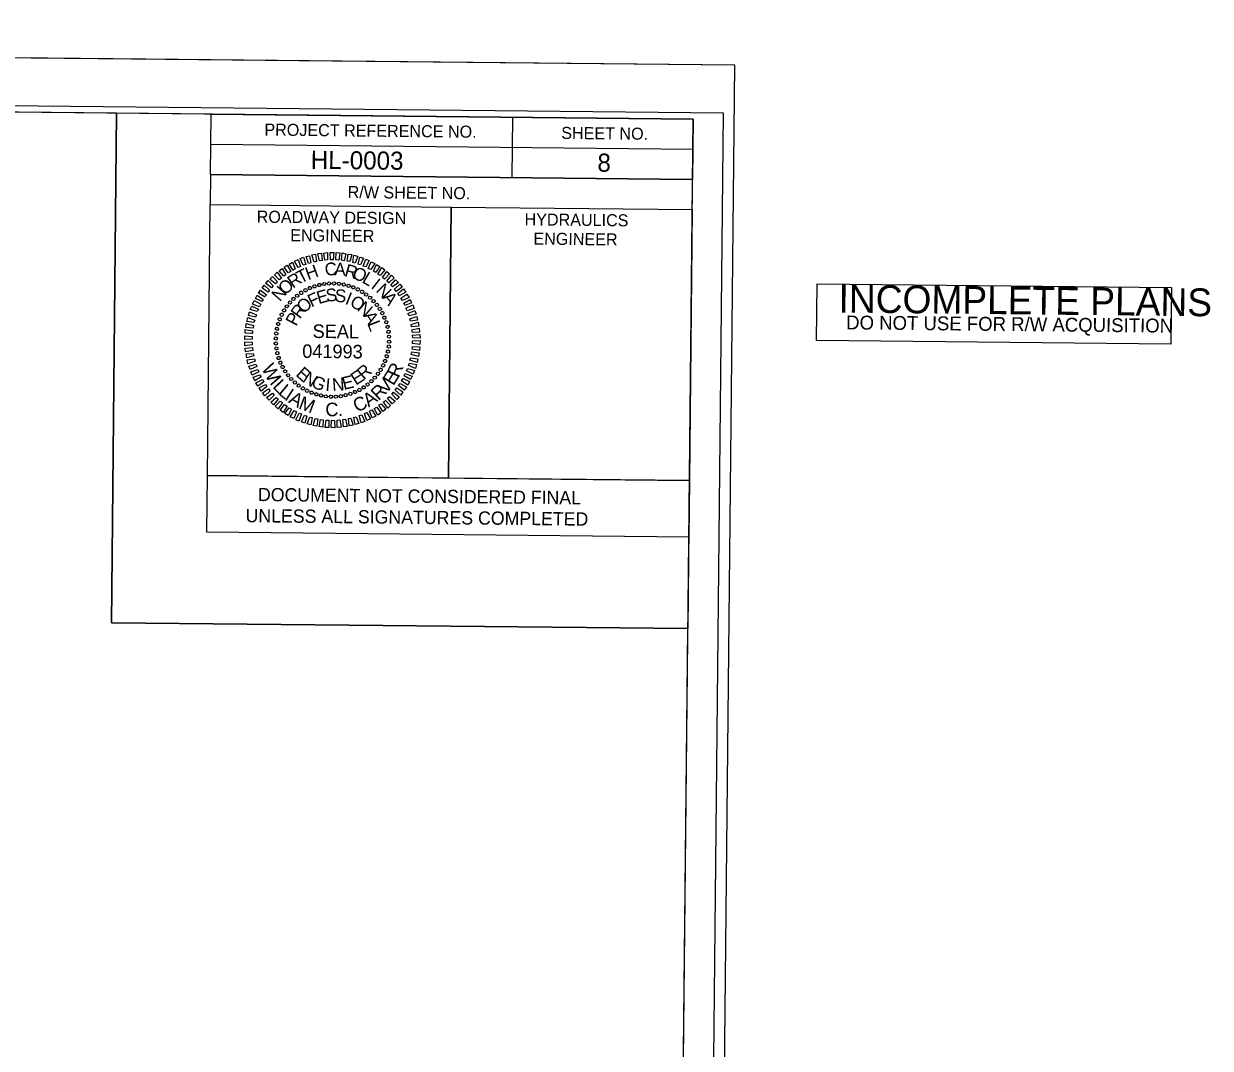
# Model space of a CAD drawing. Extents: x 928111 to 937215, y 684176 to 686530.
# Drawn here: x 934364.7 to 934857, y 684862.8 to 685288 of the extents above; entities that cross this region are included whole.
import ezdxf

# ---------------------------------------------------------------- set-up
doc = ezdxf.new("R2010")
doc.units = 0
for name, color, linetype in [('Default', 7, 'Continuous'), ('Sheet Cutting Line CELL', 7, 'Continuous'), ('Sheet Data Field CELL', 7, 'Continuous'), ('Sheet Plan CELL', 7, 'Continuous'), ('Sheet Plan Layout CELL', 7, 'Continuous'), ('Sheet Plot Border Inside CELL', 7, 'Continuous'), ('Sheet Plot Border Outside CELL', 7, 'Continuous')]:
    doc.layers.add(name, color=color, linetype=linetype)

msp = doc.modelspace()

# ---------------------------------------------------------------- linework, layer by layer
at = {"layer": 'Default'}
for p, q in [((934489.37, 685179.94), (934489.37, 685179.94)), ((934491.39, 685180.2), (934491.39, 685180.2)), ((934493.45, 685180.23), (934493.45, 685180.23)), ((934495.51, 685180.06), (934495.51, 685180.06)), ((934478.17, 685175.18), (934478.17, 685175.18)), ((934479.82, 685176.33), (934479.82, 685176.33)), ((934481.61, 685177.39), (934481.61, 685177.39)), ((934483.45, 685178.31), (934483.45, 685178.31)), ((934485.33, 685179.04), (934485.33, 685179.04)), ((934487.31, 685179.59), (934487.31, 685179.59)), ((934497.53, 685179.72), (934497.53, 685179.72)), ((934499.49, 685179.27), (934499.49, 685179.27)), ((934501.45, 685178.6), (934501.45, 685178.6)), ((934503.32, 685177.73), (934503.32, 685177.73)), ((934505.14, 685176.78), (934505.14, 685176.78)), ((934506.81, 685175.59), (934506.81, 685175.59)), ((934473.9, 685170.72), (934473.9, 685170.72)), ((934475.18, 685172.35), (934475.18, 685172.35)), ((934476.61, 685173.79), (934476.61, 685173.79)), ((934508.44, 685174.31), (934508.44, 685174.31)), ((934509.88, 685172.89), (934509.88, 685172.89)), ((934511.27, 685171.32), (934511.27, 685171.32)), ((934470.89, 685165.36), (934470.89, 685165.36)), ((934471.76, 685167.23), (934471.76, 685167.23)), ((934472.71, 685169.05), (934472.71, 685169.05)), ((934512.42, 685169.67), (934512.42, 685169.67)), ((934513.48, 685167.88), (934513.48, 685167.88)), ((934514.4, 685166.04), (934514.4, 685166.04)), ((934469.78, 685161.44), (934469.78, 685161.44)), ((934470.22, 685163.4), (934470.22, 685163.4)), ((934515.13, 685164.16), (934515.13, 685164.16)), ((934515.68, 685162.18), (934515.68, 685162.18)), ((934469.27, 685157.36), (934469.27, 685157.36)), ((934469.29, 685155.3), (934469.29, 685155.3)), ((934469.43, 685159.42), (934469.43, 685159.42)), ((934492.79, 685156.7), (934492.79, 685156.7)), ((934516.03, 685160.12), (934516.03, 685160.12)), ((934516.29, 685158.1), (934516.29, 685158.1)), ((934516.32, 685156.04), (934516.32, 685156.04)), ((934469.55, 685153.28), (934469.55, 685153.28)), ((934469.91, 685151.21), (934469.91, 685151.21)), ((934515.81, 685151.96), (934515.81, 685151.96)), ((934516.16, 685153.98), (934516.16, 685153.98)), ((934470.45, 685149.24), (934470.45, 685149.24)), ((934471.18, 685147.36), (934471.18, 685147.36)), ((934472.1, 685145.52), (934472.1, 685145.52)), ((934513.83, 685146.17), (934513.83, 685146.17)), ((934514.69, 685148.04), (934514.69, 685148.04)), ((934515.36, 685150), (934515.36, 685150)), ((934473.16, 685143.73), (934473.16, 685143.73)), ((934474.31, 685142.08), (934474.31, 685142.08)), ((934475.7, 685140.51), (934475.7, 685140.51)), ((934510.4, 685141.05), (934510.4, 685141.05)), ((934511.68, 685142.68), (934511.68, 685142.68)), ((934512.87, 685144.35), (934512.87, 685144.35)), ((934477.14, 685139.09), (934477.14, 685139.09)), ((934478.77, 685137.81), (934478.77, 685137.81)), ((934480.44, 685136.62), (934480.44, 685136.62)), ((934482.26, 685135.67), (934482.26, 685135.67)), ((934503.97, 685136.01), (934503.97, 685136.01)), ((934505.76, 685137.07), (934505.76, 685137.07)), ((934507.42, 685138.22), (934507.42, 685138.22)), ((934508.98, 685139.61), (934508.98, 685139.61)), ((934484.13, 685134.8), (934484.13, 685134.8)), ((934486.09, 685134.13), (934486.09, 685134.13)), ((934488.06, 685133.68), (934488.06, 685133.68)), ((934490.07, 685133.34), (934490.07, 685133.34)), ((934492.13, 685133.17), (934492.13, 685133.17)), ((934494.19, 685133.2), (934494.19, 685133.2)), ((934496.21, 685133.46), (934496.21, 685133.46)), ((934498.28, 685133.81), (934498.28, 685133.81)), ((934500.25, 685134.36), (934500.25, 685134.36)), ((934502.13, 685135.09), (934502.13, 685135.09))]:
    msp.add_line(p, q, dxfattribs=at)
for points in [[(934478.52, 685186.8), (934477.05, 685189.44), (934478.51, 685190.08), (934479.56, 685187.21)], [(934480.59, 685187.76), (934479.4, 685190.49), (934480.81, 685191.04), (934481.77, 685188.03)], [(934482.9, 685188.49), (934481.85, 685191.31), (934483.3, 685191.72), (934483.88, 685188.81)], [(934485.15, 685189.08), (934484.2, 685192.04), (934485.8, 685192.35), (934486.14, 685189.3)], [(934487.41, 685189.57), (934486.69, 685192.58), (934488.24, 685192.7), (934488.53, 685189.7)], [(934489.66, 685189.83), (934489.18, 685192.83), (934490.77, 685193), (934490.79, 685189.96)], [(934492.01, 685190.04), (934491.8, 685193.09), (934493.35, 685193.02), (934493.13, 685189.98)], [(934494.26, 685189.97), (934494.29, 685193.01), (934495.83, 685192.95), (934495.38, 685189.91)], [(934496.6, 685189.8), (934496.82, 685192.85), (934498.36, 685192.55), (934497.72, 685189.6)], [(934498.84, 685189.41), (934499.3, 685192.4), (934500.84, 685192.15), (934499.97, 685189.25)], [(934501.23, 685188.87), (934501.73, 685191.91), (934503.32, 685191.52), (934502.21, 685188.62)], [(934503.47, 685188.23), (934504.21, 685191.13), (934505.65, 685190.65), (934504.45, 685187.89)], [(934505.57, 685187.37), (934506.68, 685190.31), (934507.99, 685189.73), (934506.65, 685187.03)], [(934470.73, 685181.72), (934468.69, 685183.81), (934469.83, 685184.92), (934471.63, 685182.37)], [(934472.62, 685183.16), (934470.63, 685185.43), (934471.91, 685186.4), (934473.52, 685183.76)], [(934474.42, 685184.55), (934472.71, 685186.95), (934473.94, 685187.83), (934475.46, 685185.1)], [(934476.49, 685185.7), (934474.78, 685188.24), (934476.25, 685188.98), (934477.39, 685186.25)], [(934507.67, 685186.46), (934508.87, 685189.21), (934510.32, 685188.54), (934508.7, 685185.93)], [(934509.82, 685185.36), (934511.11, 685188.01), (934512.51, 685187.2), (934510.7, 685184.78)], [(934511.63, 685184.07), (934513.3, 685186.77), (934514.51, 685185.78), (934512.66, 685183.5)], [(934513.54, 685182.65), (934515.3, 685185.21), (934516.51, 685184.16), (934514.43, 685181.98)], [(934467.51, 685178.33), (934465.09, 685180.19), (934466.14, 685181.4), (934468.18, 685179.17)], [(934469.17, 685180.1), (934466.8, 685182.04), (934467.98, 685183.11), (934469.93, 685180.84)], [(934515.31, 685181.17), (934517.25, 685183.59), (934518.37, 685182.46), (934516.19, 685180.46)], [(934516.98, 685179.52), (934519.02, 685181.7), (934520.13, 685180.56), (934517.67, 685178.76)], [(934518.6, 685177.81), (934520.78, 685179.9), (934521.75, 685178.62), (934519.25, 685176.87)], [(934463.52, 685172.7), (934460.86, 685173.9), (934461.57, 685175.35), (934464.09, 685173.59)], [(934464.66, 685174.71), (934462.05, 685176.14), (934463, 685177.44), (934465.42, 685175.54)], [(934466.09, 685176.57), (934463.57, 685178.19), (934464.48, 685179.54), (934466.71, 685177.45)], [(934519.99, 685175.97), (934522.31, 685177.91), (934523.18, 685176.55), (934520.54, 685175.07)], [(934521.19, 685174.04), (934523.69, 685175.79), (934524.57, 685174.38), (934521.84, 685173.09)], [(934461.6, 685168.5), (934458.7, 685169.38), (934459.32, 685170.82), (934462.12, 685169.48)], [(934462.56, 685170.56), (934459.66, 685171.66), (934460.38, 685173.11), (934463.04, 685171.58)], [(934522.39, 685171.96), (934525.03, 685173.57), (934525.62, 685172.11), (934522.94, 685171.06)], [(934523.3, 685169.94), (934526.08, 685171.31), (934526.68, 685169.81), (934523.76, 685168.9)], [(934460.24, 685164.02), (934457.34, 685164.42), (934457.68, 685166.01), (934460.62, 685165)], [(934460.87, 685166.26), (934457.97, 685166.9), (934458.32, 685168.44), (934461.26, 685167.24)], [(934524.12, 685167.72), (934527, 685168.91), (934527.5, 685167.45), (934524.58, 685166.73)], [(934524.85, 685165.47), (934527.86, 685166.51), (934528.13, 685164.96), (934525.17, 685164.48)], [(934459.58, 685159.38), (934456.54, 685159.51), (934456.65, 685161.05), (934459.69, 685160.51)], [(934459.84, 685161.63), (934456.84, 685161.94), (934457.05, 685163.53), (934460.09, 685162.75)], [(934525.39, 685163.21), (934528.35, 685164.07), (934528.62, 685162.47), (934525.66, 685162.22)], [(934525.79, 685160.96), (934528.84, 685161.58), (934528.97, 685159.99), (934525.97, 685159.83)], [(934459.53, 685154.7), (934456.48, 685154.35), (934456.41, 685155.95), (934459.45, 685155.82)], [(934459.51, 685157.04), (934456.46, 685156.93), (934456.48, 685158.52), (934459.52, 685158.16)], [(934526.05, 685158.7), (934529.1, 685159.05), (934529.18, 685157.45), (934526.13, 685157.58)], [(934526.07, 685156.36), (934529.12, 685156.47), (934529.1, 685154.88), (934526.06, 685155.23)], [(934459.79, 685152.44), (934456.74, 685151.82), (934456.61, 685153.41), (934459.62, 685153.57)], [(934460.19, 685150.19), (934457.23, 685149.33), (934456.96, 685150.93), (934459.92, 685151.18)], [(934525.74, 685151.77), (934528.74, 685151.46), (934528.54, 685149.87), (934525.5, 685150.65)], [(934526, 685154.02), (934529.05, 685153.89), (934528.94, 685152.35), (934525.89, 685152.89)], [(934460.73, 685147.93), (934457.72, 685146.89), (934457.45, 685148.44), (934460.41, 685148.92)], [(934461.46, 685145.68), (934458.59, 685144.49), (934458.09, 685145.94), (934461, 685146.66)], [(934524.71, 685147.14), (934527.61, 685146.5), (934527.27, 685144.96), (934524.33, 685146.16)], [(934525.34, 685149.38), (934528.25, 685148.98), (934527.9, 685147.39), (934524.96, 685148.4)], [(934462.28, 685143.46), (934459.5, 685142.09), (934458.91, 685143.59), (934461.82, 685144.5)], [(934463.2, 685141.44), (934460.55, 685139.83), (934459.96, 685141.28), (934462.64, 685142.34)], [(934522.07, 685140.7), (934524.73, 685139.5), (934524.01, 685138.05), (934521.49, 685139.81)], [(934523.03, 685142.84), (934525.92, 685141.74), (934525.2, 685140.29), (934522.55, 685141.82)], [(934523.98, 685144.9), (934526.88, 685144.02), (934526.26, 685142.58), (934523.46, 685143.92)], [(934464.39, 685139.36), (934461.89, 685137.61), (934461.01, 685139.02), (934463.75, 685140.31)], [(934465.59, 685137.43), (934463.28, 685135.48), (934462.4, 685136.85), (934465.04, 685138.33)], [(934466.98, 685135.59), (934464.8, 685133.5), (934463.83, 685134.78), (934466.33, 685136.53)], [(934519.5, 685136.83), (934522.01, 685135.21), (934521.11, 685133.86), (934518.88, 685135.95)], [(934520.92, 685138.69), (934523.53, 685137.26), (934522.58, 685135.96), (934520.16, 685137.86)], [(934468.6, 685133.88), (934466.57, 685131.7), (934465.45, 685132.84), (934467.91, 685134.64)], [(934470.27, 685132.23), (934468.33, 685129.81), (934467.21, 685130.94), (934469.39, 685132.94)], [(934472.04, 685130.75), (934470.28, 685128.19), (934469.07, 685129.24), (934471.16, 685131.42)], [(934514.85, 685131.68), (934516.89, 685129.59), (934515.75, 685128.48), (934513.95, 685131.03)], [(934516.41, 685133.3), (934518.78, 685131.35), (934517.6, 685130.29), (934515.65, 685132.56)], [(934518.07, 685135.07), (934520.49, 685133.21), (934519.45, 685132), (934517.41, 685134.23)], [(934473.95, 685129.33), (934472.28, 685126.63), (934471.07, 685127.62), (934472.92, 685129.9)], [(934475.76, 685128.04), (934474.47, 685125.39), (934473.07, 685126.2), (934474.88, 685128.62)], [(934477.91, 685126.94), (934476.71, 685124.19), (934475.26, 685124.86), (934476.88, 685127.47)], [(934480.01, 685126.03), (934478.9, 685123.09), (934477.59, 685123.67), (934478.93, 685126.37)], [(934507.06, 685126.6), (934508.54, 685123.96), (934507.08, 685123.32), (934506.03, 685126.19)], [(934509.09, 685127.7), (934510.8, 685125.15), (934509.34, 685124.42), (934508.19, 685127.15)], [(934511.16, 685128.85), (934512.87, 685126.45), (934511.65, 685125.57), (934510.13, 685128.3)], [(934512.96, 685130.24), (934514.95, 685127.97), (934513.68, 685127), (934512.06, 685129.64)], [(934482.11, 685125.17), (934481.38, 685122.27), (934479.93, 685122.75), (934481.13, 685125.5)], [(934484.35, 685124.53), (934483.85, 685121.49), (934482.26, 685121.88), (934483.37, 685124.78)], [(934486.74, 685123.99), (934486.29, 685121), (934484.74, 685121.25), (934485.61, 685124.15)], [(934488.98, 685123.6), (934488.76, 685120.55), (934487.22, 685120.85), (934487.86, 685123.8)], [(934491.33, 685123.43), (934491.29, 685120.39), (934489.75, 685120.45), (934490.2, 685123.49)], [(934493.58, 685123.36), (934493.78, 685120.31), (934492.23, 685120.38), (934492.45, 685123.42)], [(934495.92, 685123.57), (934496.41, 685120.57), (934494.81, 685120.4), (934494.79, 685123.44)], [(934498.17, 685123.83), (934498.89, 685120.82), (934497.35, 685120.7), (934497.05, 685123.7)], [(934500.43, 685124.32), (934501.38, 685121.36), (934499.79, 685121.05), (934499.44, 685124.1)], [(934502.69, 685124.91), (934503.73, 685122.09), (934502.28, 685121.68), (934501.7, 685124.59)], [(934504.99, 685125.64), (934506.18, 685122.9), (934504.77, 685122.36), (934503.81, 685125.37)]]:
    msp.add_lwpolyline(points, close=True, dxfattribs=at)
for centre, major_axis in [((934487.34, 685179.57), (-0.157, 0.657)), ((934489.35, 685179.96), (-0.099, 0.668)), ((934491.39, 685180.17), (-0.04, 0.674)), ((934493.44, 685180.2), (0.019, 0.675)), ((934495.49, 685180.06), (0.077, 0.671)), ((934497.51, 685179.73), (0.136, 0.661)), ((934499.5, 685179.23), (0.193, 0.647)), ((934478.18, 685175.12), (-0.419, 0.529)), ((934479.84, 685176.33), (-0.372, 0.563)), ((934481.6, 685177.38), (-0.321, 0.594)), ((934483.45, 685178.28), (-0.268, 0.619)), ((934485.36, 685179.01), (-0.213, 0.64)), ((934501.44, 685178.56), (0.248, 0.628)), ((934503.31, 685177.73), (0.302, 0.604)), ((934505.11, 685176.73), (0.354, 0.575)), ((934506.81, 685175.58), (0.402, 0.542)), ((934508.4, 685174.29), (0.448, 0.505)), ((934473.91, 685170.71), (-0.542, 0.402)), ((934475.2, 685172.31), (-0.505, 0.448)), ((934476.63, 685173.78), (-0.464, 0.49)), ((934509.87, 685172.86), (0.49, 0.464)), ((934511.21, 685171.31), (0.529, 0.419)), ((934512.42, 685169.65), (0.563, 0.372)), ((934470.93, 685165.35), (-0.628, 0.248)), ((934471.76, 685167.22), (-0.604, 0.302)), ((934472.76, 685169.02), (-0.575, 0.354)), ((934513.47, 685167.89), (0.594, 0.321)), ((934514.37, 685166.04), (0.619, 0.268)), ((934469.76, 685161.42), (-0.661, 0.136)), ((934470.26, 685163.41), (-0.647, 0.193)), ((934515.1, 685164.13), (0.64, 0.213)), ((934515.66, 685162.15), (0.657, 0.157)), ((934516.05, 685160.14), (0.668, 0.099)), ((934469.29, 685157.35), (-0.675, 0.019)), ((934469.32, 685155.3), (-0.674, -0.04)), ((934469.43, 685159.4), (-0.671, 0.077)), ((934516.26, 685158.1), (0.674, 0.04)), ((934516.29, 685156.05), (0.675, -0.019)), ((934469.53, 685153.26), (-0.668, -0.099)), ((934469.92, 685151.25), (-0.657, -0.157)), ((934515.33, 685149.99), (0.647, -0.193)), ((934515.82, 685151.98), (0.661, -0.136)), ((934516.15, 685154), (0.671, -0.077)), ((934470.48, 685149.27), (-0.64, -0.213)), ((934471.21, 685147.36), (-0.619, -0.268)), ((934472.11, 685145.51), (-0.594, -0.321)), ((934513.82, 685146.18), (0.604, -0.302)), ((934514.65, 685148.05), (0.628, -0.248)), ((934473.16, 685143.75), (-0.563, -0.372)), ((934474.37, 685142.09), (-0.529, -0.419)), ((934475.71, 685140.54), (-0.49, -0.464)), ((934510.38, 685141.09), (0.505, -0.448)), ((934511.67, 685142.69), (0.542, -0.402)), ((934512.82, 685144.38), (0.575, -0.354)), ((934477.18, 685139.11), (-0.448, -0.505)), ((934478.78, 685137.82), (-0.402, -0.542)), ((934480.48, 685136.67), (-0.354, -0.575)), ((934482.27, 685135.67), (-0.302, -0.604)), ((934484.14, 685134.84), (-0.248, -0.628)), ((934502.13, 685135.12), (0.268, -0.619)), ((934503.98, 685136.02), (0.321, -0.594)), ((934505.74, 685137.07), (0.372, -0.563)), ((934507.4, 685138.28), (0.419, -0.529)), ((934508.95, 685139.62), (0.464, -0.49)), ((934486.08, 685134.17), (-0.193, -0.647)), ((934488.07, 685133.67), (-0.136, -0.661)), ((934490.09, 685133.34), (-0.077, -0.671)), ((934492.14, 685133.2), (-0.019, -0.675)), ((934494.19, 685133.23), (0.04, -0.674)), ((934496.23, 685133.44), (0.099, -0.668)), ((934498.25, 685133.83), (0.157, -0.657)), ((934500.22, 685134.39), (0.213, -0.64))]:
    msp.add_ellipse(centre, major_axis=major_axis, ratio=0.999708, dxfattribs=at)
at = {"layer": 'Sheet Cutting Line CELL'}
msp.add_line((934659.7, 685270.75), (932976.29, 685287.96), dxfattribs=at)
at = {"layer": 'Sheet Plan CELL'}
for p, q in [((934567.44, 685249.14), (934567.23, 685224.14)), ((934442.29, 685237.94), (934642.33, 685235.89)), ((934442.17, 685225.41), (934442.05, 685212.92)), ((934442.17, 685225.41), (934642.2, 685223.39)), ((934442.17, 685225.41), (934642.2, 685223.39)), ((934542.09, 685211.9), (934540.95, 685099.44)), ((934440.67, 685076.94), (934440.91, 685100.44)), ((934440.91, 685100.44), (934640.94, 685098.39)), ((934640.94, 685098.38), (934640.7, 685074.88)), ((934640.7, 685074.89), (934440.67, 685076.94))]:
    msp.add_line(p, q, dxfattribs=at)
for points in [[(934642.5, 685248.43), (933142.54, 685263.77), (933131.8, 684213.83), (934631.73, 684198.49)], [(934401.06, 685039.4), (934640.32, 685036.96), (934642.51, 685248.43), (934403.22, 685250.88)], [(934442.43, 685250.49), (934642.5, 685248.43), (934642.2, 685223.39), (934442.17, 685225.41)], [(934442.05, 685212.92), (934542.09, 685211.9), (934540.94, 685099.39), (934440.91, 685100.44)], [(934542.09, 685211.9), (934642.07, 685210.89), (934640.94, 685098.38), (934540.94, 685099.39)], [(934693.66, 685156.53), (934693.9, 685180.03), (934840.89, 685178.52), (934840.65, 685155.02)]]:
    msp.add_lwpolyline(points, close=True, dxfattribs=at)
at = {"layer": 'Sheet Plan Layout CELL'}
msp.add_lwpolyline([(933142.51, 685263.75), (933131.8, 684213.83), (934631.72, 684198.49), (934640.3, 685036.96), (934401.06, 685039.4), (934403.22, 685250.88)], close=True, dxfattribs=at)
at = {"layer": 'Sheet Plot Border Inside CELL'}
msp.add_lwpolyline([(932978.29, 684212.89), (934644.19, 684195.86), (934654.99, 685250.79), (932989.08, 685267.83)], close=True, dxfattribs=at)
at = {"layer": 'Sheet Plot Border Outside CELL'}
msp.add_lwpolyline([(932965.09, 684193.02), (934648.5, 684175.8), (934659.7, 685270.75), (932976.29, 685287.96)], close=True, dxfattribs=at)

# ---------------------------------------------------------------- texts
at = {"layer": 'Default'}
for s, height, rotation, p in [('T', 5.29, 27.2339, (934479.62, 685179.99)), ('H', 5.29, 20.0336, (934482.68, 685181.51)), ('C', 5.29, 5.634, (934489.83, 685183.31)), ('A', 5.29, 358.4344, (934493.53, 685183.55)), ('R', 5.29, 344.0352, (934497.47, 685183.33)), ('O', 5.29, 336.8353, (934500.6, 685182.59)), ('L', 5.29, 329.635, (934504.71, 685180.81)), ('O', 5.29, 41.6359, (934473.15, 685175.09)), ('R', 5.29, 34.4346, (934476.41, 685177.96)), ('I', 5.29, 322.4343, (934508.48, 685178.52)), ('N', 5.29, 315.233, (934510.48, 685177.05)), ('N', 5.29, 48.8376, (934470.97, 685172.39)), ('F', 5.29, 25.3811, (934484.07, 685170.2)), ('E', 5.29, 16.0252, (934487.08, 685171.57)), ('S', 5.29, 6.6697, (934490.33, 685172.52)), ('S', 5.29, 357.3145, (934493.7, 685172.53)), ('I', 5.29, 338.6037, (934497.73, 685171.84)), ('O', 5.29, 329.2476, (934499.6, 685171.16)), ('A', 5.29, 308.0313, (934513.22, 685174.26)), ('R', 5.29, 53.4538, (934479.28, 685165.18)), ('O', 5.29, 44.0954, (934480.95, 685167.46)), ('N', 5.29, 319.8907, (934502.72, 685169.26)), ('P', 5.29, 62.813, (934477.75, 685162.2)), ('A', 5.29, 301.1744, (934505.36, 685166.79)), ('SEAL', 5.623, 359.4141, (934484.55, 685157.58)), ('L', 5.29, 291.815, (934507.16, 685163.54)), ('041993', 5.623, 359.4141, (934480.24, 685149.32)), ('W', 5.62, 297.7715, (934463.23, 685145.04)), ('E', 5.29, 317.691, (934477.27, 685142.19)), ('R', 5.29, 41.8955, (934505.84, 685139.92)), ('R', 5.62, 66.1105, (934520.28, 685140.75)), ('I', 5.62, 310.3056, (934466.46, 685138.9)), ('L', 5.62, 314.1075, (934467.7, 685137.19)), ('N', 5.29, 327.0481, (934480.05, 685139.63)), ('G', 5.29, 336.4044, (934483.59, 685137.48)), ('I', 5.29, 355.1153, (934489.72, 685135.64)), ('N', 5.29, 4.4705, (934492.86, 685135.46)), ('E', 5.29, 13.8259, (934497.5, 685135.98)), ('E', 5.29, 32.5382, (934502.49, 685137.76)), ('V', 5.62, 50.7482, (934515.07, 685134.03)), ('E', 5.62, 59.0012, (934518.09, 685137.47)), ('L', 5.62, 320.3823, (934469.98, 685134.57)), ('I', 5.62, 326.6571, (934472.54, 685132.21)), ('R', 5.62, 43.2679, (934511.93, 685131.33)), ('A', 5.62, 330.459, (934474.21, 685130.92)), ('M', 5.62, 339.2993, (934478.39, 685128.37)), ('C', 5.62, 1.0292, (934489.9, 685125.05)), ('C', 5.62, 24.8455, (934502.93, 685126.58)), ('A', 5.62, 34.4276, (934507.8, 685128.69)), ('.', 5.62, 10.6113, (934495.21, 685125.01))]:
    msp.add_text(s, height=height, rotation=rotation, dxfattribs=at).set_placement(p)
at = {"layer": 'Sheet Data Field CELL'}
for s, p in [('HL-0003', (934483.77, 685227.74)), ('8', (934602.7, 685226.59))]:
    msp.add_text(s, height=7.5, rotation=359.4141, dxfattribs=at).set_placement(p)
at = {"layer": 'Sheet Plan CELL'}
for s, height, p in [('PROJECT REFERENCE NO.', 5.0001, (934464.54, 685241.54)), ('SHEET NO.', 5, (934587.7, 685240.17)), ('R/W SHEET NO.', 5.0001, (934499.08, 685215.64)), ('ROADWAY DESIGN', 5.0001, (934461.35, 685205.42)), ('HYDRAULICS', 5, (934572.48, 685204.31)), ('ENGINEER', 5, (934475.26, 685197.74)), ('ENGINEER', 5, (934576.16, 685196.31)), ('INCOMPLETE PLANS', 11.52, (934702.73, 685168.14)), ('DO NOT USE FOR R/W ACQUISITION', 5.76, (934705.9, 685161.15)), ('DOCUMENT NOT CONSIDERED FINAL', 5.5, (934461.87, 685089.88)), ('UNLESS ALL SIGNATURES COMPLETED', 5.5, (934456.71, 685081.13))]:
    msp.add_text(s, height=height, rotation=359.4141, dxfattribs=at).set_placement(p)

doc.saveas('drawing.dxf')
